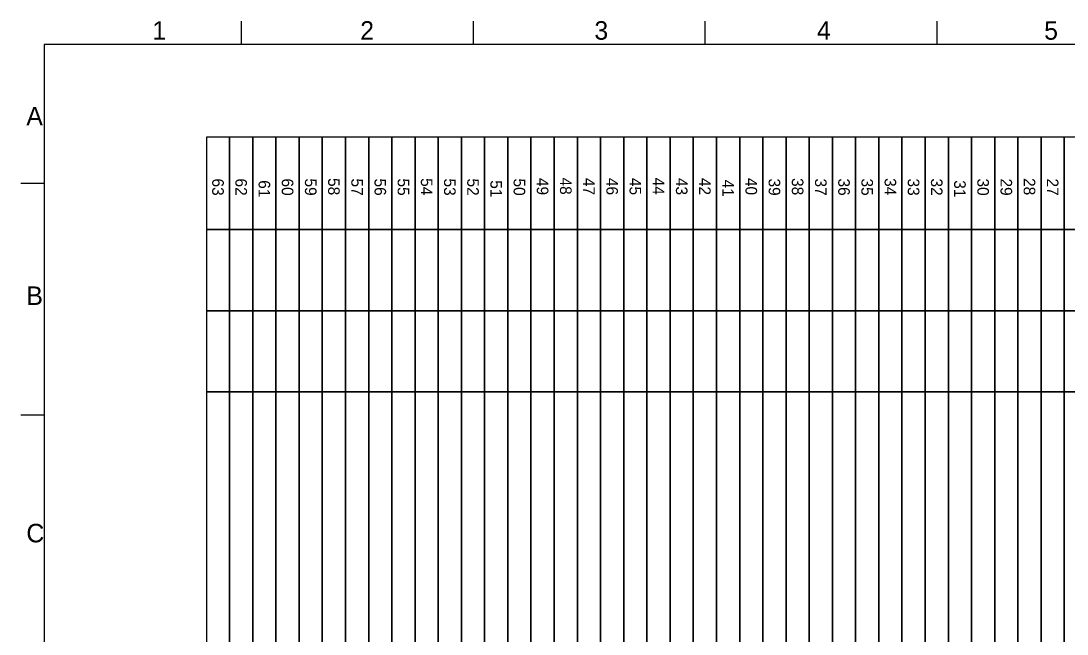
# Model space of a CAD drawing. Extents: x 0 to 395, y 0 to 270.
# Drawn here: x 0 to 225.6, y 137.7 to 270.1 of the extents above; entities that cross this region are included whole.
import ezdxf

# ---------------------------------------------------------------- set-up
doc = ezdxf.new("R2010")
doc.units = 0
doc.layers.add('90_Plankopf', color=7, linetype='Continuous')

msp = doc.modelspace()

# ---------------------------------------------------------------- linework, layer by layer
at = {"layer": '90_Plankopf'}
for p, q in [((47.5, 270), (47.5, 265)), ((97.5, 270), (97.5, 265)), ((147.5, 270), (147.5, 265)), ((197.5, 270), (197.5, 265)), ((390, 265), (5, 265)), ((5, 265), (5, 5)), ((0, 235), (5, 235)), ((0, 185), (5, 185))]:
    msp.add_line(p, q, dxfattribs=at)
for points in [[(40, 245), (40, 225), (45, 225), (45, 245)], [(45, 245), (45, 225), (50, 225), (50, 245)], [(50, 245), (50, 225), (55, 225), (55, 245)], [(55, 245), (55, 225), (60, 225), (60, 245)], [(60, 245), (60, 225), (65, 225), (65, 245)], [(65, 245), (65, 225), (70, 225), (70, 245)], [(70, 245), (70, 225), (75, 225), (75, 245)], [(75, 245), (75, 225), (80, 225), (80, 245)], [(80, 245), (80, 225), (85, 225), (85, 245)], [(85, 245), (85, 225), (90, 225), (90, 245)], [(90, 245), (90, 225), (95, 225), (95, 245)], [(95, 245), (95, 225), (100, 225), (100, 245)], [(100, 245), (100, 225), (105, 225), (105, 245)], [(105, 245), (105, 225), (110, 225), (110, 245)], [(110, 245), (110, 225), (115, 225), (115, 245)], [(115, 245), (115, 225), (120, 225), (120, 245)], [(120, 245), (120, 225), (125, 225), (125, 245)], [(125, 245), (125, 225), (130, 225), (130, 245)], [(130, 245), (130, 225), (135, 225), (135, 245)], [(135, 245), (135, 225), (140, 225), (140, 245)], [(140, 245), (140, 225), (145, 225), (145, 245)], [(145, 245), (145, 225), (150, 225), (150, 245)], [(150, 245), (150, 225), (155, 225), (155, 245)], [(155, 245), (155, 225), (160, 225), (160, 245)], [(160, 245), (160, 225), (165, 225), (165, 245)], [(165, 245), (165, 225), (170, 225), (170, 245)], [(170, 245), (170, 225), (175, 225), (175, 245)], [(175, 245), (175, 225), (180, 225), (180, 245)], [(180, 245), (180, 225), (185, 225), (185, 245)], [(185, 245), (185, 225), (190, 225), (190, 245)], [(190, 245), (190, 225), (195, 225), (195, 245)], [(195, 245), (195, 225), (200, 225), (200, 245)], [(200, 245), (200, 225), (205, 225), (205, 245)], [(205, 245), (205, 225), (210, 225), (210, 245)], [(210, 245), (210, 225), (215, 225), (215, 245)], [(215, 245), (215, 225), (220, 225), (220, 245)], [(220, 245), (220, 225), (225, 225), (225, 245)], [(225, 245), (225, 225), (230, 225), (230, 245)], [(40, 225), (40, 207.5), (45, 207.5), (45, 225)], [(45, 225), (45, 207.5), (50, 207.5), (50, 225)], [(50, 225), (50, 207.5), (55, 207.5), (55, 225)], [(55, 225), (55, 207.5), (60, 207.5), (60, 225)], [(60, 225), (60, 207.5), (65, 207.5), (65, 225)], [(65, 225), (65, 207.5), (70, 207.5), (70, 225)], [(70, 225), (70, 207.5), (75, 207.5), (75, 225)], [(75, 225), (75, 207.5), (80, 207.5), (80, 225)], [(80, 225), (80, 207.5), (85, 207.5), (85, 225)], [(85, 225), (85, 207.5), (90, 207.5), (90, 225)], [(90, 225), (90, 207.5), (95, 207.5), (95, 225)], [(95, 225), (95, 207.5), (100, 207.5), (100, 225)], [(100, 225), (100, 207.5), (105, 207.5), (105, 225)], [(105, 225), (105, 207.5), (110, 207.5), (110, 225)], [(110, 225), (110, 207.5), (115, 207.5), (115, 225)], [(115, 225), (115, 207.5), (120, 207.5), (120, 225)], [(120, 225), (120, 207.5), (125, 207.5), (125, 225)], [(125, 225), (125, 207.5), (130, 207.5), (130, 225)], [(130, 225), (130, 207.5), (135, 207.5), (135, 225)], [(135, 225), (135, 207.5), (140, 207.5), (140, 225)], [(140, 225), (140, 207.5), (145, 207.5), (145, 225)], [(145, 225), (145, 207.5), (150, 207.5), (150, 225)], [(150, 225), (150, 207.5), (155, 207.5), (155, 225)], [(155, 225), (155, 207.5), (160, 207.5), (160, 225)], [(160, 225), (160, 207.5), (165, 207.5), (165, 225)], [(165, 225), (165, 207.5), (170, 207.5), (170, 225)], [(170, 225), (170, 207.5), (175, 207.5), (175, 225)], [(175, 225), (175, 207.5), (180, 207.5), (180, 225)], [(180, 225), (180, 207.5), (185, 207.5), (185, 225)], [(185, 225), (185, 207.5), (190, 207.5), (190, 225)], [(190, 225), (190, 207.5), (195, 207.5), (195, 225)], [(195, 225), (195, 207.5), (200, 207.5), (200, 225)], [(200, 225), (200, 207.5), (205, 207.5), (205, 225)], [(205, 225), (205, 207.5), (210, 207.5), (210, 225)], [(210, 225), (210, 207.5), (215, 207.5), (215, 225)], [(215, 225), (215, 207.5), (220, 207.5), (220, 225)], [(220, 225), (220, 207.5), (225, 207.5), (225, 225)], [(225, 225), (225, 207.5), (230, 207.5), (230, 225)], [(40, 207.5), (40, 190), (45, 190), (45, 207.5)], [(45, 207.5), (45, 190), (50, 190), (50, 207.5)], [(50, 207.5), (50, 190), (55, 190), (55, 207.5)], [(55, 207.5), (55, 190), (60, 190), (60, 207.5)], [(60, 207.5), (60, 190), (65, 190), (65, 207.5)], [(65, 207.5), (65, 190), (70, 190), (70, 207.5)], [(70, 207.5), (70, 190), (75, 190), (75, 207.5)], [(75, 207.5), (75, 190), (80, 190), (80, 207.5)], [(80, 207.5), (80, 190), (85, 190), (85, 207.5)], [(85, 207.5), (85, 190), (90, 190), (90, 207.5)], [(90, 207.5), (90, 190), (95, 190), (95, 207.5)], [(95, 207.5), (95, 190), (100, 190), (100, 207.5)], [(100, 207.5), (100, 190), (105, 190), (105, 207.5)], [(105, 207.5), (105, 190), (110, 190), (110, 207.5)], [(110, 207.5), (110, 190), (115, 190), (115, 207.5)], [(115, 207.5), (115, 190), (120, 190), (120, 207.5)], [(120, 207.5), (120, 190), (125, 190), (125, 207.5)], [(125, 207.5), (125, 190), (130, 190), (130, 207.5)], [(130, 207.5), (130, 190), (135, 190), (135, 207.5)], [(135, 207.5), (135, 190), (140, 190), (140, 207.5)], [(140, 207.5), (140, 190), (145, 190), (145, 207.5)], [(145, 207.5), (145, 190), (150, 190), (150, 207.5)], [(150, 207.5), (150, 190), (155, 190), (155, 207.5)], [(155, 207.5), (155, 190), (160, 190), (160, 207.5)], [(160, 207.5), (160, 190), (165, 190), (165, 207.5)], [(165, 207.5), (165, 190), (170, 190), (170, 207.5)], [(170, 207.5), (170, 190), (175, 190), (175, 207.5)], [(175, 207.5), (175, 190), (180, 190), (180, 207.5)], [(180, 207.5), (180, 190), (185, 190), (185, 207.5)], [(185, 207.5), (185, 190), (190, 190), (190, 207.5)], [(190, 207.5), (190, 190), (195, 190), (195, 207.5)], [(195, 207.5), (195, 190), (200, 190), (200, 207.5)], [(200, 207.5), (200, 190), (205, 190), (205, 207.5)], [(205, 207.5), (205, 190), (210, 190), (210, 207.5)], [(210, 207.5), (210, 190), (215, 190), (215, 207.5)], [(215, 207.5), (215, 190), (220, 190), (220, 207.5)], [(220, 207.5), (220, 190), (225, 190), (225, 207.5)], [(225, 207.5), (225, 190), (230, 190), (230, 207.5)], [(40, 190), (40, 57.5), (45, 57.5), (45, 190)], [(45, 190), (45, 57.5), (50, 57.5), (50, 190)], [(50, 190), (50, 57.5), (55, 57.5), (55, 190)], [(55, 190), (55, 57.5), (60, 57.5), (60, 190)], [(60, 190), (60, 57.5), (65, 57.5), (65, 190)], [(65, 190), (65, 57.5), (70, 57.5), (70, 190)], [(70, 190), (70, 57.5), (75, 57.5), (75, 190)], [(75, 190), (75, 57.5), (80, 57.5), (80, 190)], [(80, 190), (80, 57.5), (85, 57.5), (85, 190)], [(85, 190), (85, 57.5), (90, 57.5), (90, 190)], [(90, 190), (90, 57.5), (95, 57.5), (95, 190)], [(95, 190), (95, 57.5), (100, 57.5), (100, 190)], [(100, 190), (100, 57.5), (105, 57.5), (105, 190)], [(105, 190), (105, 57.5), (110, 57.5), (110, 190)], [(110, 190), (110, 57.5), (115, 57.5), (115, 190)], [(115, 190), (115, 57.5), (120, 57.5), (120, 190)], [(120, 190), (120, 57.5), (125, 57.5), (125, 190)], [(125, 190), (125, 57.5), (130, 57.5), (130, 190)], [(130, 190), (130, 57.5), (135, 57.5), (135, 190)], [(135, 190), (135, 57.5), (140, 57.5), (140, 190)], [(140, 190), (140, 57.5), (145, 57.5), (145, 190)], [(145, 190), (145, 57.5), (150, 57.5), (150, 190)], [(150, 190), (150, 57.5), (155, 57.5), (155, 190)], [(155, 190), (155, 57.5), (160, 57.5), (160, 190)], [(160, 190), (160, 57.5), (165, 57.5), (165, 190)], [(165, 190), (165, 57.5), (170, 57.5), (170, 190)], [(170, 190), (170, 57.5), (175, 57.5), (175, 190)], [(175, 190), (175, 57.5), (180, 57.5), (180, 190)], [(180, 190), (180, 57.5), (185, 57.5), (185, 190)], [(185, 190), (185, 57.5), (190, 57.5), (190, 190)], [(190, 190), (190, 57.5), (195, 57.5), (195, 190)], [(195, 190), (195, 57.5), (200, 57.5), (200, 190)], [(200, 190), (200, 57.5), (205, 57.5), (205, 190)], [(205, 190), (205, 57.5), (210, 57.5), (210, 190)], [(210, 190), (210, 57.5), (215, 57.5), (215, 190)], [(215, 190), (215, 57.5), (220, 57.5), (220, 190)], [(220, 190), (220, 57.5), (225, 57.5), (225, 190)], [(225, 190), (225, 57.5), (230, 57.5), (230, 190)]]:
    msp.add_lwpolyline(points, close=True, dxfattribs=at)

# ---------------------------------------------------------------- texts
for s, p in [('1', (28.33, 266)), ('2', (73.17, 266)), ('3', (123.67, 266)), ('4', (171.67, 266)), ('5', (220.67, 266)), ('A', (1.17, 247.5)), ('B', (1.17, 208.75)), ('C', (1.17, 157.5))]:
    msp.add_text(s, height=4, dxfattribs=at).set_placement(p)
for s, p in [(' 63', (41.25, 236.98)), (' 62', (46.25, 236.98)), (' 61', (51.25, 236.6)), (' 60', (56.25, 236.98)), (' 59', (61.25, 236.98)), (' 58', (66.25, 237.07)), (' 57', (71.25, 236.98)), (' 56', (76.25, 236.98)), (' 55', (81.25, 236.98)), (' 54', (86.25, 237.05)), (' 53', (91.25, 236.98)), (' 52', (96.25, 236.98)), (' 51', (101.25, 236.6)), (' 50', (106.25, 236.98)), (' 49', (111.25, 237.11)), (' 48', (116.25, 237.19)), (' 47', (121.25, 237.11)), (' 46', (126.25, 237.11)), (' 45', (131.25, 237.11)), (' 44', (136.25, 237.18)), (' 43', (141.25, 237.11)), (' 42', (146.25, 237.11)), (' 41', (151.25, 236.73)), (' 40', (156.25, 237.11)), (' 39', (161.25, 236.98)), (' 38', (166.25, 237.07)), (' 37', (171.25, 236.98)), (' 36', (176.25, 236.98)), (' 35', (181.25, 236.98)), (' 34', (186.25, 237.05)), (' 33', (191.25, 236.98)), (' 32', (196.25, 236.98)), (' 31', (201.25, 236.6)), (' 30', (206.25, 236.98)), (' 29', (211.25, 236.98)), (' 28', (216.25, 237.07)), (' 27', (221.25, 236.98))]:
    msp.add_text(s, height=2.5, rotation=270, dxfattribs=at).set_placement(p)

doc.saveas('drawing.dxf')
